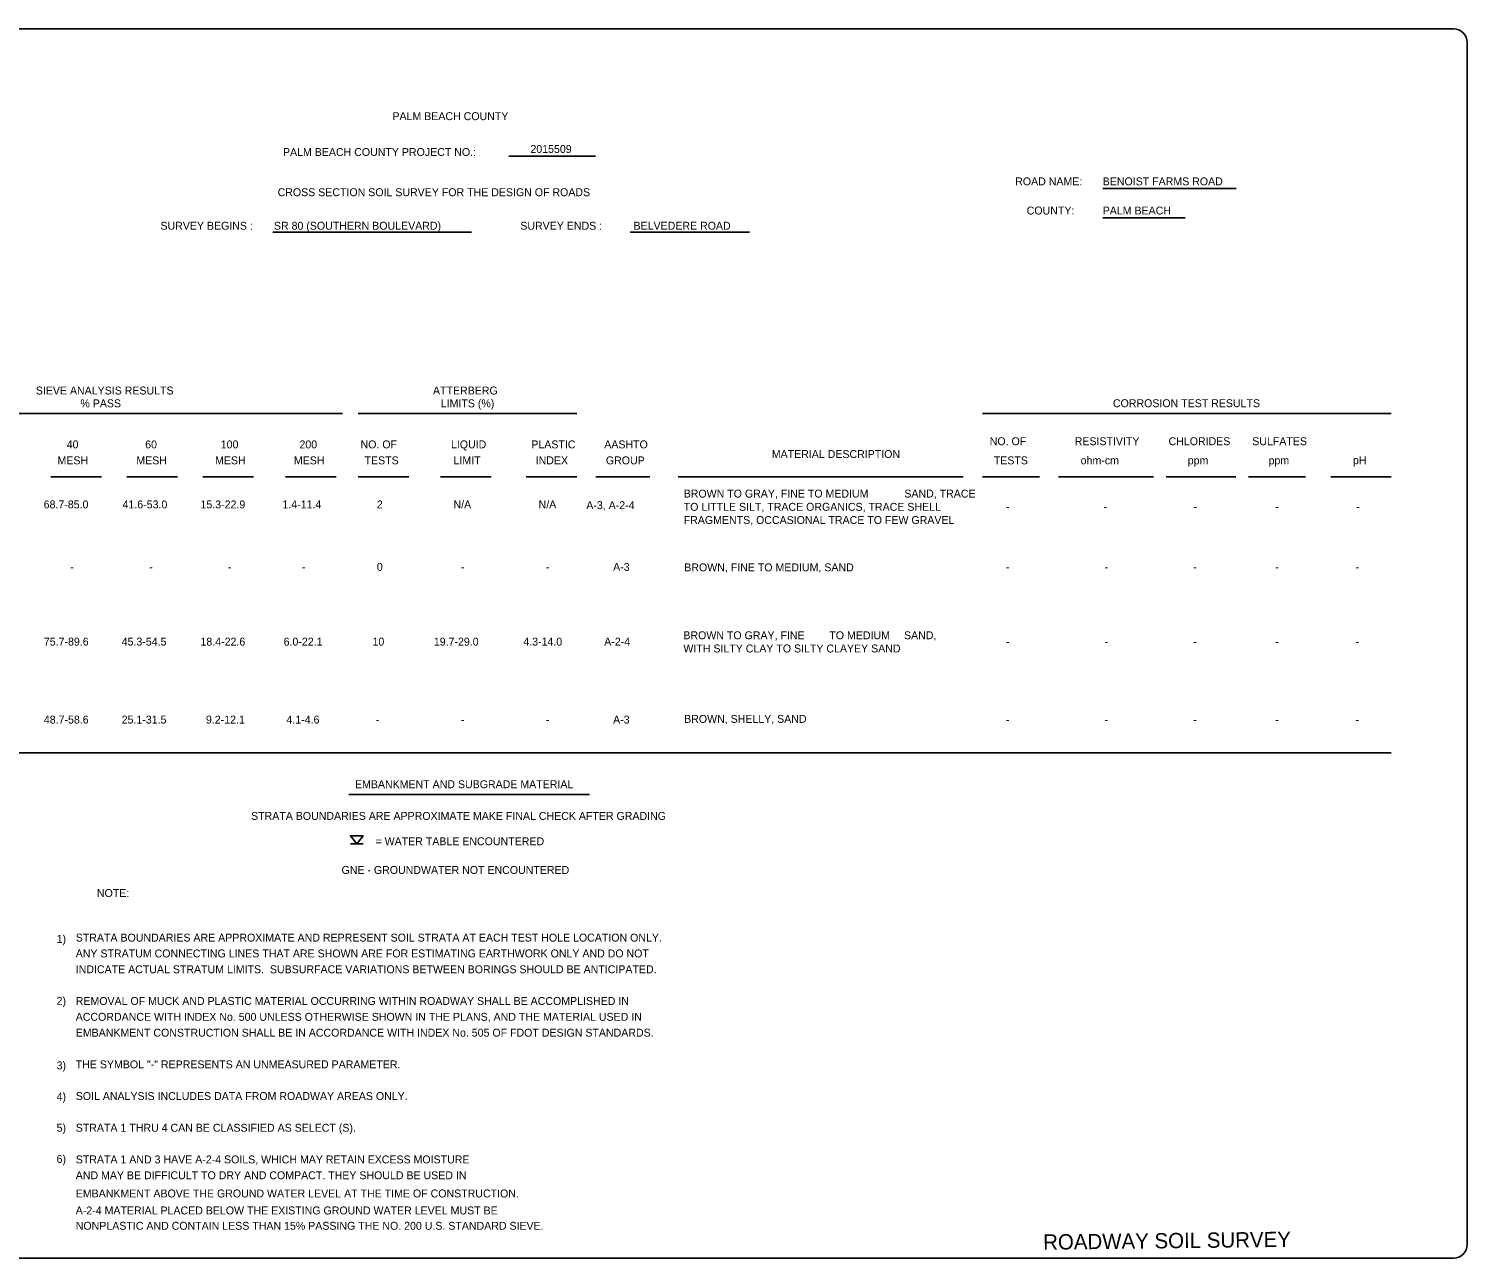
# Model space of a CAD drawing. Extents: x 0 to 331, y -72 to 117.
# Drawn here: x 126.61 to 149.31, y 97.27 to 116.66 of the extents above; entities that cross this region are included whole.
import ezdxf

# ---------------------------------------------------------------- set-up
doc = ezdxf.new("R2010")
doc.units = 0
for name, color, linetype in [('Baseline of Survey', 7, 'Continuous'), ('Default', 7, 'Continuous'), ('GeotechMisc', 7, 'Continuous'), ('Level 0', 7, 'Continuous')]:
    doc.layers.add(name, color=color, linetype=linetype)

# ---------------------------------------------------------------- blocks, each defined once
blk = doc.blocks.new('DOTGW_21')
at = {"layer": 'Default'}
for p, q in [((-7.25, 1.96), (-4.08, 1.96)), ((-5.66, -0.02), (-7.25, 1.96)), ((-4.08, 1.96), (-5.66, -0.02)), ((-7.25, -0.02), (-4.08, -0.02))]:
    blk.add_line(p, q, dxfattribs=at)
for points in [[(-5.66, -0.02), (-4.08, 1.96), (-7.25, 1.96), (-5.66, -0.02)], [(-7.25, 1.96), (-4.08, 1.96), (-5.66, -0.02), (-7.25, 1.96)]]:
    blk.add_lwpolyline(points, dxfattribs=at)

msp = doc.modelspace()

# ---------------------------------------------------------------- linework, layer by layer
at = {"layer": 'Baseline of Survey'}
for p, q in [((149.092, 116.664), (116.35, 116.664)), ((149.31, 97.484), (149.31, 116.447)), ((149.092, 97.266), (116.35, 97.266))]:
    msp.add_line(p, q, dxfattribs=at)
for centre, start, end in [((149.092, 116.447), 0, 90), ((149.092, 97.484), 270, 0)]:
    msp.add_arc(centre, 0.218, start, end, dxfattribs=at)
at = {"layer": 'GeotechMisc'}
for p, q in [((134.182, 114.657), (135.551, 114.657)), ((143.557, 114.144), (145.661, 114.144)), ((143.557, 113.684), (144.857, 113.684)), ((124.257, 110.594), (131.557, 110.594)), ((131.807, 110.594), (135.257, 110.594)), ((141.657, 110.594), (148.107, 110.594)), ((119.774, 105.242), (148.107, 105.242)), ((131.657, 104.582), (135.457, 104.582))]:
    msp.add_line(p, q, dxfattribs=at)
for points in [[(126.957, 109.594), (127.757, 109.594)], [(128.157, 109.594), (128.957, 109.594)], [(129.357, 109.594), (130.157, 109.594)], [(130.657, 109.594), (131.457, 109.594)], [(131.807, 109.594), (132.607, 109.594)], [(133.107, 109.594), (133.907, 109.594)], [(134.457, 109.594), (135.257, 109.594)], [(135.557, 109.594), (136.407, 109.594)], [(136.857, 109.594), (141.357, 109.594)], [(141.657, 109.594), (142.557, 109.594)], [(142.857, 109.594), (144.357, 109.594)], [(144.557, 109.594), (145.657, 109.594)], [(145.857, 109.594), (146.757, 109.594)], [(147.157, 109.594), (148.107, 109.594)]]:
    msp.add_lwpolyline(points, dxfattribs=at)
at = {"layer": 'Level 0'}
for p, q in [((130.462, 113.453), (133.596, 113.453)), ((136.099, 113.453), (137.98, 113.453))]:
    msp.add_line(p, q, dxfattribs=at)

# ---------------------------------------------------------------- block references
at = {"layer": 'GeotechMisc', "xscale": 0.06299212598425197, "yscale": 0.06299212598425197}
msp.add_blockref('DOTGW_21', (132.141, 103.806), dxfattribs=at)

# ---------------------------------------------------------------- texts
at = {"layer": 'GeotechMisc'}
for s, p in [('PALM BEACH COUNTY', (132.347, 115.223)), ('PALM BEACH COUNTY PROJECT NO.:', (130.62, 114.657)), ('2015509', (134.525, 114.705)), ('ROAD NAME:', (142.176, 114.194)), ('BENOIST FARMS ROAD', (143.557, 114.194)), ('CROSS SECTION SOIL SURVEY FOR THE DESIGN OF ROADS', (130.535, 114.023)), ('COUNTY:', (142.357, 113.734)), ('PALM BEACH', (143.557, 113.734)), ('SURVEY BEGINS :', (128.686, 113.494)), ('SR 80 (SOUTHERN BOULEVARD)', (130.477, 113.494)), ('SURVEY ENDS :', (134.365, 113.494)), ('BELVEDERE ROAD', (136.152, 113.494)), ('SIEVE ANALYSIS RESULTS', (126.719, 110.894)), ('ATTERBERG', (132.987, 110.894)), ('% PASS', (127.423, 110.692)), ('LIMITS (%)', (133.11, 110.692)), ('CORROSION TEST RESULTS', (143.718, 110.694)), ('40', (127.206, 110.044)), ('60', (128.445, 110.044)), ('100', (129.638, 110.044)), ('200', (130.88, 110.044)), ('NO. OF', (131.844, 110.044)), ('LIQUID', (133.271, 110.044)), ('PLASTIC', (134.539, 110.044)), ('AASHTO', (135.69, 110.044)), ('NO. OF', (141.774, 110.094)), ('RESISTIVITY', (143.115, 110.094)), ('CHLORIDES', (144.596, 110.094)), ('SULFATES', (145.917, 110.094)), ('MESH', (127.061, 109.792)), ('MESH', (128.305, 109.792)), ('MESH', (129.548, 109.792)), ('MESH', (130.792, 109.792)), ('TESTS', (131.907, 109.792)), ('LIMIT', (133.312, 109.792)), ('INDEX', (134.608, 109.792)), ('GROUP', (135.716, 109.792)), ('MATERIAL DESCRIPTION', (138.334, 109.892)), ('TESTS', (141.838, 109.792)), ('ohm-cm', (143.209, 109.792)), ('ppm', (144.899, 109.792)), ('ppm', (146.174, 109.792)), ('pH', (147.507, 109.794)), ('68.7-85.0', (126.843, 109.097)), ('41.6-53.0', (128.088, 109.097)), ('15.3-22.9', (129.318, 109.097)), ('1.4-11.4', (130.611, 109.097)), ('2', (132.101, 109.097)), ('N/A', (133.311, 109.097)), ('N/A', (134.654, 109.097)), ('A-3, A-2-4', (135.407, 109.085)), ('BROWN TO GRAY, FINE TO MEDIUM', (136.944, 109.268)), ('SAND, TRACE', (140.426, 109.268)), ('TO LITTLE SILT, TRACE ORGANICS, TRACE SHELL', (136.944, 109.059)), ('FRAGMENTS, OCCASIONAL TRACE TO FEW GRAVEL', (136.944, 108.851)), ('-', (142.029, 109.061)), ('-', (143.569, 109.061)), ('-', (144.99, 109.061)), ('-', (146.278, 109.061)), ('-', (147.557, 109.061)), ('-', (127.261, 108.112)), ('-', (128.507, 108.112)), ('-', (129.751, 108.112)), ('-', (130.917, 108.112)), ('0', (132.101, 108.112)), ('-', (133.427, 108.112)), ('-', (134.77, 108.112)), ('A-3', (135.83, 108.112)), ('BROWN, FINE TO MEDIUM, SAND ', (136.953, 108.104)), ('-', (142.029, 108.112)), ('-', (143.586, 108.112)), ('-', (144.985, 108.112)), ('-', (146.281, 108.112)), ('-', (147.546, 108.112)), ('BROWN TO GRAY, FINE ', (136.939, 107.032)), ('TO MEDIUM ', (139.243, 107.032)), ('SAND,', (140.421, 107.032)), ('75.7-89.6', (126.846, 106.932)), ('45.3-54.5', (128.074, 106.932)), ('18.4-22.6', (129.318, 106.932)), ('6.0-22.1', (130.63, 106.932)), ('10', (132.033, 106.932)), ('19.7-29.0', (133.001, 106.932)), ('4.3-14.0', (134.413, 106.932)), ('A-2-4', (135.69, 106.932)), ('WITH SILTY CLAY TO SILTY CLAYEY SAND ', (136.939, 106.824)), ('-', (142.029, 106.932)), ('-', (143.586, 106.932)), ('-', (144.985, 106.932)), ('-', (146.281, 106.932)), ('-', (147.546, 106.932)), ('48.7-58.6', (126.846, 105.702)), ('25.1-31.5', (128.074, 105.702)), ('9.2-12.1', (129.404, 105.702)), ('4.1-4.6', (130.675, 105.702)), ('A-3', (135.83, 105.702)), ('BROWN, SHELLY, SAND ', (136.951, 105.713)), ('-', (132.083, 105.702)), ('-', (133.427, 105.702)), ('-', (134.77, 105.702)), ('-', (142.029, 105.702)), ('-', (143.586, 105.702)), ('-', (144.985, 105.702)), ('-', (146.281, 105.702)), ('-', (147.546, 105.702)), ('EMBANKMENT AND SUBGRADE MATERIAL', (131.756, 104.682)), ('STRATA BOUNDARIES ARE APPROXIMATE MAKE FINAL CHECK AFTER GRADING', (130.116, 104.182)), ('= WATER TABLE ENCOUNTERED', (132.08, 103.782)), ('GNE - GROUNDWATER NOT ENCOUNTERED', (131.544, 103.329)), ('NOTE:', (127.683, 102.965)), ('STRATA BOUNDARIES ARE APPROXIMATE AND REPRESENT SOIL STRATA AT EACH TEST HOLE LOCATION ONLY.', (127.349, 102.262)), ('1)', (127.047, 102.242)), ('ANY STRATUM CONNECTING LINES THAT ARE SHOWN ARE FOR ESTIMATING EARTHWORK ONLY AND DO NOT', (127.349, 102.012)), ('INDICATE ACTUAL STRATUM LIMITS.  SUBSURFACE VARIATIONS BETWEEN BORINGS SHOULD BE ANTICIPATED.', (127.349, 101.762)), ('2)', (127.047, 101.264)), ('REMOVAL OF MUCK AND PLASTIC MATERIAL OCCURRING WITHIN ROADWAY SHALL BE ACCOMPLISHED IN', (127.349, 101.262)), ('ACCORDANCE WITH INDEX No. 500 UNLESS OTHERWISE SHOWN IN THE PLANS, AND THE MATERIAL USED IN', (127.349, 101.012)), ('EMBANKMENT CONSTRUCTION SHALL BE IN ACCORDANCE WITH INDEX No. 505 OF FDOT DESIGN STANDARDS.', (127.349, 100.762)), ('3)', (127.047, 100.246)), ('THE SYMBOL "-" REPRESENTS AN UNMEASURED PARAMETER.', (127.349, 100.262)), ('SOIL ANALYSIS INCLUDES DATA FROM ROADWAY AREAS ONLY.', (127.349, 99.762)), ('4)', (127.047, 99.754)), ('5)', (127.047, 99.262)), ('STRATA 1 THRU 4 CAN BE CLASSIFIED AS SELECT (S).', (127.349, 99.262)), ('6)', (127.047, 98.77)), ('STRATA 1 AND 3 HAVE A-2-4 SOILS, WHICH MAY RETAIN EXCESS MOISTURE', (127.349, 98.762)), ('AND MAY BE DIFFICULT TO DRY AND COMPACT. THEY SHOULD BE USED IN ', (127.349, 98.512)), ('EMBANKMENT ABOVE THE GROUND WATER LEVEL AT THE TIME OF CONSTRUCTION. ', (127.349, 98.225)), ('A-2-4 MATERIAL PLACED BELOW THE EXISTING GROUND WATER LEVEL MUST BE', (127.349, 97.957)), ('NONPLASTIC AND CONTAIN LESS THAN 15%%% PASSING THE NO. 200 U.S. STANDARD SIEVE.', (127.349, 97.715))]:
    msp.add_text(s, height=0.125, dxfattribs=at).set_placement(p)
at = {"layer": 'Level 0'}
msp.add_text('ROADWAY SOIL SURVEY ', height=0.24136, rotation=0.6548, dxfattribs=at).set_placement((142.618, 97.4))

doc.saveas('drawing.dxf')
